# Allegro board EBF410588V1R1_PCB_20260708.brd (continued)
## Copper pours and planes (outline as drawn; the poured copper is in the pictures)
3V3_OUT on BOTTOM: 66.5,8.26 67.87,8.26 68.12,8 68.12,7.54 68.45,7.21 69.01,7.21 69.16,7.06 69.16,5.66 69.32,5.51 71.27,5.51 71.45,5.33 71.45,3.33 71.27,3.15 70.26,3.15 70.03,3.38 70.03,4.27 69.77,4.52 67.74,4.52 67.51,4.75 67.51,7.06 67.31,7.26 66.6,7.26 66.5,7.37
5V_OUT on BOTTOM: 71.17,8.26 72.54,8.26 72.69,8.1 72.69,7.8 73.3,7.19 73.74,7.19 73.86,7.06 73.86,5.79 74.17,5.49 75.11,5.49 75.29,5.31 75.29,3.43 75.03,3.17 74.12,3.17 73.86,3.43 73.86,4.45 73.48,4.83 72.31,4.83 72.21,4.93 72.21,7.14 72.01,7.34 71.32,7.34 71.17,7.49
12V on TOP: 9.53,71.93 18.69,71.93 18.97,71.65 18.97,67.54 19.13,67.39 19.74,67.39 19.74,65.58 19.53,65.38 17.5,65.38 17.5,66.09 17.07,66.52 17.07,68.96 16.87,69.16 13.61,69.16 13.41,68.96 13.41,67.54 13.59,67.36 14.25,67.36 14.25,66.4 13.97,66.12 13.97,65.56 13.79,65.38 11.91,65.38 11.91,66.4 11.48,66.83 11.48,69.8 11.2,70.08 9.53,70.08
12V on BOTTOM: 32.41,56.59 33.6,56.59 33.76,56.74 33.76,57.94 33.58,58.12 32.44,58.12 32.23,57.91 32.23,56.77
12V on BOTTOM: 88.7,8.69 90.35,8.69 90.35,7.47 90.07,7.19 86.41,7.19 86.41,8.46 88.47,8.46
12V on BOTTOM: 106.15,23.98 106.27,24.1 110.06,24.1 110.34,23.83 110.34,22.63 108.13,22.63 107.9,22.4 107.9,20.57 107.72,20.4 105.36,20.4 105.13,20.62 105.13,22.05 105.33,22.25 105.84,22.25 106.15,22.56
12V on BOTTOM: 22.48,58.78 22.17,58.78 22,58.6 22,57.45 22.38,57.07 23.67,57.07 23.67,57.89 22.81,57.89 22.66,58.04 22.66,58.6
12V on BOTTOM: 13.51,72.75 13.51,69.67 13.74,69.44 15.98,69.44 16.21,69.67 16.21,72.21 15.27,72.21 15.11,72.36 15.11,72.67 15.04,72.75
12V on ART04: 46.1,58.06 48.56,55.6 48.56,49.56 49.99,48.13 70.61,48.13 71.04,47.7 71.04,31.9 72.52,30.43 99.95,30.43 100.97,29.41 100.97,22.48 101.27,22.17 107.34,22.17 107.65,21.87 107.65,16.38 107.29,16.03 96.77,16.03 96.19,15.44 96.19,9.12 94.54,7.47 86.69,7.47 86.44,7.72 86.44,20.7 84.96,22.17 64.95,22.17 64.16,22.96 64.16,42.04 62.81,43.38 42.57,43.38 40.34,45.62 40.34,50.04 39.98,50.39 33.81,50.39 33.68,50.27 22.3,50.27 21.95,50.62 21.95,64.41 21.67,64.69 13.72,64.69 13.49,64.92 13.49,72.67 13.97,73.15 26.49,73.15 27.15,72.49 27.15,58.42 27.51,58.06
12V_OUT on BOTTOM: 76.78,7.04 76.78,5.11 76.99,4.9 77.72,4.9 78,4.62 78,3.2 78.18,3.02 79.65,3.02 79.86,3.23 79.86,6.17 80.04,6.35 82.32,6.35 82.5,6.53 82.5,8.48 78.38,8.48 78.38,7.29 78.13,7.04
GND on TOP: outline of 98 points within 1.4,49.83 94.97,83.16 ; 63 cut-outs
GND on TOP: 139.01,47.98 94.72,47.98 93.88,48.82 93.88,51.36 93.07,52.17 91.44,52.17 91.87,52.6 91.87,74.8 94.64,77.57 94.64,82.4 94.79,82.55 142.14,82.55 142.7,81.99 142.7,51.66 ; 47 cut-outs
GND on TOP: 40.67,52.17 84.86,52.17 84.94,52.1 84.94,46.79 84.56,46.41 82.35,46.41 82.09,46.15 82.09,42.75 74.8,35.46 36.42,35.46 36.32,35.36 36.32,35.13 36.2,35 36.32,35 36.32,32.28 36.53,32.08 37.57,32.08 37.62,32.03 37.62,30.78 37.8,30.78 37.8,31.85 37.81,31.84 39.54,31.84 39.55,31.85 40.92,31.85 41.4,31.37 42.57,32.54 84.86,32.54 84.94,32.46 84.94,28.47 84.73,28.27 81.79,28.27 81.64,28.12 81.64,10.92 79.76,10.92 79.76,10.79 81.64,10.79 81.64,8.59 76.76,8.59 76.33,8.15 72.92,8.15 71.55,9.53 68.66,9.53 68.22,9.09 71.73,5.59 81.64,5.59 81.64,2.44 81.18,1.98 25.93,1.98 24.71,3.2 8.86,3.2 7.44,4.62 7.44,8.43 7.04,8.84 2.01,8.84 1.3,9.55 1.3,49.94 1.52,50.16 38.66,50.16 ; 80 cut-outs
GND on TOP: 3,0.51 1.24,1.24 0.51,3 0.51,58.42 1.57,58.42 1.57,9.88 2.34,9.12 3,9.12 3.02,9.14 7.26,9.14 7.82,8.59 7.82,4.8 9.12,3.51 25.04,3.51 26.21,2.34 142.16,2.34 142.54,2.72 142.54,20.45 143.36,20.45 143.61,20.7 143.61,27.15 143.43,27.33 142.54,27.33 142.54,31.17 148.89,31.17 148.89,40.51 142.54,40.51 142.54,46.94 141.15,46.94 141,47.09 141,47.8 142.54,49.35 142.54,81.97 142.11,82.4 90.3,82.4 90.3,87.45 54.2,87.45 54.2,82.4 33.99,82.4 33.53,82.85 33.53,85.85 33.12,86.26 30.51,86.26 30.43,86.18 30.43,84.68 30.51,84.61 31.47,84.61 32.32,83.76 32.32,82.18 32.05,81.92 30.71,81.92 30.56,82.07 30.56,82.09 30.25,82.4 7.7,82.4 7.37,82.07 7.37,75.13 6.76,74.52 6.76,69.8 7.8,68.76 7.8,65.76 7.16,65.13 1.78,65.13 1.27,64.62 1.27,58.52 0.51,58.52 0.51,87 1.24,88.76 3,89.49 147,89.49 148.76,88.76 149.49,87 149.49,3 148.76,1.24 147,0.51 ; 10 cut-outs
GND on TOP: 142.7,46.18 142.7,40.64 149.02,40.64 149.02,39.65 134.9,39.65 134.9,32.03 149,32.03 149,32.66 135.53,32.66 135.53,38.96 149.07,38.96 149.07,31.01 142.67,31.01 142.67,28.3 143.48,27.48 143.48,2.74 142.88,2.13 81.69,2.13 81.28,2.54 81.28,4.98 81.66,5.36 81.66,5.38 81.69,5.41 115.04,5.41 116.81,7.19 119.43,7.19 119.63,7.39 119.63,9.6 119.56,9.68 118.14,9.68 117.5,9.04 116.2,9.04 115.37,8.2 115.24,8.33 115.24,9.27 114.58,9.93 112.55,9.93 111.48,8.86 109.27,8.86 108.56,8.15 81.28,8.15 81.28,13.34 82.04,13.34 82.04,13.36 81.28,13.36 81.28,28.14 81.48,28.35 84.73,28.35 84.58,28.5 84.58,32.41 81.1,32.41 81.08,32.44 77.8,32.44 77.7,32.54 77.7,32.77 78.13,33.2 78.16,33.2 84.58,39.62 84.58,52.02 84.84,52.27 93.6,52.27 94.03,51.84 94.03,48.95 94.69,48.29 138.35,48.29 140.49,46.15 141.2,46.15 141.22,46.18 ; 62 cut-outs
GND on BOTTOM: 51.59,83.13 51.59,76.61 53.16,75.03 53.16,58.88 72.34,58.88 72.92,58.29 83.64,58.29 84.73,57.2 84.73,50.83 85.29,50.27 98.32,50.27 98.86,50.8 98.55,51.1 98.55,58.6 97.79,59.36 95.43,59.36 95.02,59.77 95.02,60.48 96.47,61.93 106.2,61.93 108.43,59.69 108.43,51.97 145.36,51.97 146.43,53.04 146.43,80.42 143.41,83.44 51.89,83.44 ; 39 cut-outs
GND on BOTTOM: 67.84,48.77 67.84,46.05 66.98,45.19 64.57,45.19 64.57,45.54 67.79,48.77
GND on BOTTOM: 3,0.51 1.24,1.24 0.51,3 0.51,81.38 3.56,81.38 3.91,81.03 3.91,20.78 3.61,20.47 3.61,17.91 3.66,17.86 3.81,17.86 3.91,17.75 4.65,17.75 5,18.11 50.24,18.11 50.24,18.08 51.16,17.17 51.79,17.17 52.02,16.94 52.02,14.25 52.17,14.1 53.04,14.1 53.54,14.61 55.27,14.61 55.6,14.94 55.6,15.8 56.44,16.64 56.44,17.6 56.69,17.86 57.58,17.86 58.24,17.2 61.67,17.2 62.31,16.56 62.31,15.54 63.22,14.63 63.22,11.91 64.39,10.74 65.05,10.74 65.25,10.95 65.25,15.47 65.63,15.85 77.04,15.85 77.34,15.54 77.34,11.1 77.62,10.82 80.49,10.82 80.49,10.36 80.62,10.36 80.62,10.82 90.22,10.82 90.22,9.75 90.5,9.75 90.5,10.82 91.8,10.82 92.1,11.13 92.1,11.61 144.88,11.61 145.41,12.14 145.41,55.88 145.34,55.96 145.41,55.96 145.41,80.52 142.88,83.06 27.33,83.06 27.33,83.57 25.93,83.57 25.93,83.06 0.51,83.06 0.51,87 1.24,88.76 3,89.49 147,89.49 148.76,88.76 149.49,87 149.49,3 148.76,1.24 147,0.51 ; 55 cut-outs
GND on BOTTOM: 0.51,81 0.51,83.64 3.94,83.64 3.94,81
GND on BOTTOM: 3.56,55.98 3.56,82.96 3.96,83.36 51.99,83.36 52.22,83.13 52.22,82.52 52.2,82.5 52.2,75.62 53.34,74.47 53.34,54.94 52.4,54 44.42,54 40.08,58.34 37.69,58.34 34.9,55.55 3.99,55.55 ; 48 cut-outs
GND on BOTTOM: 144.32,53.14 145.85,53.14 145.85,12.19 145.08,11.43 117.78,11.43 116.23,12.98 115.27,12.98 113.72,11.43 92.28,11.43 92.1,11.61 92.1,15.7 90.4,17.4 87.22,17.4 86.69,17.93 86.69,22.96 83.79,25.86 63.2,25.86 60.1,28.96 47.62,28.96 46.33,30.25 46.33,31.7 46.69,32.05 61.34,32.05 64.21,29.18 89.31,29.18 89.69,28.8 89.69,18.47 89.84,18.31 92.74,18.31 93.12,18.69 93.12,28.73 93.47,29.08 93.55,29.08 93.95,29.49 97.64,29.49 97.87,29.72 97.87,31.6 97.89,31.6 98.07,31.78 98.81,31.78 99.01,31.57 99.01,31.06 100.33,29.74 103.84,29.74 104.44,30.35 120.83,30.35 121.44,29.74 122.1,29.74 122.1,33.68 121.64,34.14 121.64,38.91 121.56,38.99 112.95,38.99 111.43,40.51 108.74,40.51 108.56,40.69 108.56,52.15 108.74,52.32 143.51,52.32 ; 55 cut-outs
GND on BOTTOM: outline of 140 points within 3.68,17.73 122.28,59 ; 22 cut-outs
GND on GND02: 3,0.51 1.24,1.24 0.51,3 0.51,87 1.24,88.76 3,89.49 147,89.49 148.76,88.76 149.49,87 149.49,3 148.76,1.24 147,0.51 ; 1 cut-out
GND on ART03: 43.21,54.58 43.51,54.89 43.51,65.76 44.17,66.42 45.75,66.42 46.96,65.2 46.96,63.65 47.32,63.3 53.85,63.3 55.24,64.69 55.24,65.02 55.23,65.04 55.23,65.42 57.58,67.77 72.44,67.77 72.54,67.87 72.54,69.29 72.29,69.55 54.86,69.55 54.51,69.19 54.51,67.79 53.06,66.34 48.36,66.34 46.71,68 40.84,68 40.59,67.74 40.59,54.94 40.94,54.58
GND on ART03: 100.43,1.35 100.08,0.99 59.59,0.99 59.33,1.24 59.33,6.05 57.35,8.03 41.81,8.03 41.49,8.34 41.49,11.6 41.07,12.01 41.07,15.52 41.85,16.29 41.85,18.99 42.14,19.28 46.86,19.28 50.16,22.58 50.16,27.03 50.39,27.25 53.62,27.25 54.08,26.8 51.82,26.8 51.82,26.59 54.28,26.59 55.27,25.6 55.27,14.78 56.72,13.34 58.27,13.34 58.62,12.98 58.62,12.62 62.23,9.02 62.23,5.99 63.94,4.28 63.94,3.11 64.59,2.46 92.43,2.46 93.14,3.17 93.14,4.57 95.83,7.26 104.78,7.26 104.78,6.48 105.87,6.48 105.87,7.26 108.38,9.78 108.38,15.47 108.39,15.48 108.39,16.31 108.67,16.59 111.12,16.59 113.13,18.59 123.83,18.59 124.36,19.13 128.7,19.13 129.08,18.75 129.08,12.52 129.41,12.19 134.01,12.19 134.62,11.58 134.62,4.88 134.39,4.65 134.16,4.65 133.76,5.05 100.81,5.05 100.43,4.67 ; 4 cut-outs
GND on ART03: 92.28,48.49 92.28,53.67 91.52,54.43 91.52,55.85 90.97,56.4 91.67,57.1 91.67,61.14 91.26,61.54 91.21,61.54 90.63,62.13 90.63,62.51 89.64,63.5 89.64,86.44 89.85,86.65 146.57,86.65 147.45,85.78 147.45,19.23 147.27,19.05 145.8,19.05 145.29,19.56 139.17,19.56 138.63,20.09 138.63,20.14 136.6,22.17 134.72,22.17 134.21,22.68 132.11,22.68 130.81,23.98 115.87,23.98 115.85,24 99.03,24 98.25,24.79 98.25,29.59 97.51,30.33 97.51,31.55 96.75,32.31 96.75,34.25 93.79,34.25 92.38,32.84 92.38,20.04 92.02,19.68 92.02,18.06 92.13,17.96 94.26,17.96 94.49,17.73 94.49,16.81 94.72,16.59 108.69,16.59 108.71,16.56 108.71,9.47 108.05,8.81 107.42,8.81 107.05,9.18 93.33,9.18 93.04,8.89 93.04,5.79 92.66,5.41 86.84,5.41 86.59,5.66 86.59,12.52 87.07,13 88.27,13 88.29,12.98 89.15,12.98 90.3,14.12 90.3,33.73 91.06,34.49 91.06,44.02 91.05,44.03 91.05,46.49 91.03,46.51 91.03,47.24 ; 13 cut-outs
GND on ART03: 79.38,21.11 79.2,21.29 79.2,35.64 73.63,41.2 73.63,53.62 72.5,54.75 72.5,56.3 68.28,60.53 68.28,63.6 67.82,64.06 67.77,64.06 67.77,65.05 62.46,65.05 62.46,63.86 62.13,63.53 56.64,63.53 56.29,63.88 56.29,66.88 57.3,67.89 72.42,67.89 72.42,69.39 72.59,69.57 84.58,69.57 85.27,68.88 85.27,66.98 84.84,66.55 75.9,66.55 75.82,66.47 75.82,65.89 74.83,64.9 74.8,64.9 74.09,64.19 74.09,62.18 73.51,61.59 72.26,61.59 72.26,57.66 73.28,56.64 73.28,55.12 75.13,53.26 75.13,43.41 75.9,42.65 77.37,42.65 80.85,39.17 80.85,22.02 79.93,21.11 ; 1 cut-out
GND on ART03: outline of 152 points within 0.51,0.51 149.49,89.49 ; 8 cut-outs
GND on ART03: 58.34,15.42 58.34,13.21 58.37,13.21 59.18,12.4 62.61,12.4 63.88,13.67 66.07,13.67 66.07,14.88 65,15.95 58.88,15.95
GND on ART03: 68.22,45.85 67.36,44.98 66.78,44.98 66.14,44.35 66.14,42.06 65.61,41.53 65.53,41.53 65.53,35.81 67.72,33.63 67.72,25.7 68.12,25.3 68.12,20.52 72.14,16.51 72.14,11.43 72.82,10.74 72.82,9.63 74.83,7.62 76.58,7.62 77.01,7.19 79.71,7.19 82.35,9.83 82.35,12.42 83.17,13.25 83.17,13.53 86.79,17.14 88.85,17.14 90.27,18.57 90.42,18.57 90.5,18.49 90.5,14.94 89.71,14.15 84.96,14.15 84.48,13.67 84.48,12.47 83.92,11.91 83.92,11.18 84.48,10.62 84.48,6.6 84.4,6.53 76.63,6.53 76.28,6.88 72.09,6.88 71.58,7.39 71.58,11.53 70.46,12.65 70.46,16.08 66.34,20.19 66.34,30.91 64.26,32.99 64.26,41.94 63.37,42.82 63.37,47.73 62.61,47.73 62.26,48.08 62.26,49.33 62.84,49.91 63.83,49.91 64.64,50.72 65.07,50.72 65.53,50.27 67.11,50.27 68.22,49.15 ; 1 cut-out
GND on ART03: 56.11,57.84 65.66,57.84 71.4,52.1 71.4,39.37 75.39,35.38 75.39,18.08 75.67,17.81 80.87,17.81 83.59,20.52 83.59,42.75 82.7,43.64 82.7,43.79 81.36,45.14 81.36,48.77 80.82,49.3 80.82,50.22 79.48,51.56 79.48,56.41 79.81,56.74 81.28,56.74 81.76,56.26 81.76,53.26 82.4,52.63 82.4,49.81 82.17,49.58 82.17,48.84 84.05,46.96 84.96,46.96 85.14,46.79 85.14,44.65 84.72,44.23 85.01,43.94 85.01,17.17 84.48,16.64 75.01,16.64 74.35,17.3 74.35,19.48 74.33,19.49 74.33,25.51 74.07,25.78 73.49,25.78 73.29,25.98 73.29,30.37 72.03,31.62 72.03,35.64 72.01,35.64 71.7,35.94 71.7,37.26 71.15,37.82 70.1,37.82 69.77,38.15 69.77,52.2 65.41,56.57 63.88,56.57 63.5,56.95 57.94,56.95 57.73,56.74 57.73,56.44 59.79,54.38 59.79,53.54 59.54,53.29 56.06,53.29 55.55,53.8 55.55,57.28 ; 1 cut-out
GND on ART03: 76.33,44.96 80.62,44.96 80.8,45.14 80.8,48.9 79.86,49.83 76.3,49.83 76.07,49.61 76.07,45.21
GND on ART03: outline of 90 points within 1.04,30.78 90.47,86.65
GND on ART04: outline of 87 points within 0.51,0.51 149.49,89.49
GND on ART04: 146.25,20.88 146.25,23.29 149.49,23.29 149.49,20.88
GND on ART04: 76.05,39.19 76.35,39.5 106.35,39.5 106.93,40.08 106.93,56.62 107.29,56.97 113.61,56.97 114.25,56.34 114.25,31.06 114.96,30.35 122.35,30.35 122.76,29.95 122.76,25.27 122.4,24.92 111.79,24.92 111.53,25.17 111.53,25.45 111.56,25.48 111.56,26.59 111.23,26.92 107.95,26.92 107.72,27.15 107.72,30.48 107.49,30.71 76.66,30.71 76.05,31.32 ; 1 cut-out
GND on PWR05: 3,0.51 1.24,1.24 0.51,3 0.51,87 1.24,88.76 3,89.49 147,89.49 148.76,88.76 149.49,87 149.49,3 148.76,1.24 147,0.51
VBUS5V0_TYPEC on BOTTOM: 28.8,76.58 26.44,76.58 26.29,76.73 26.29,80.34 27.17,80.34 27.17,77.64 27.61,77.19 28.8,77.19
VBUS5V0_TYPEC on ART04: 26.26,87.91 42.16,87.91 42.52,87.55 42.52,80.98 41.94,80.39 26.31,80.39 25.55,81.15 25.55,87.2
VCC5V0_SYS_S5 on TOP: 53.16,17.83 53.39,17.6 53.39,15.82 53.64,15.57 53.64,11.68 52.2,11.68 52.2,15.32 51.87,15.65 51.87,16.05 51.71,16.21 50.95,16.21 50.83,16.33 50.83,17.7 50.95,17.83
VCC5V0_SYS_S5 on TOP: 10.03,58.34 10.03,56.95 10.95,56.95 11.28,56.62 11.28,52.78 11.56,52.5 13.82,52.5 13.94,52.63 13.94,53.95 13.77,54.13 13.28,54.13 13.11,54.31 13.11,58.12 12.88,58.34
VCC5V0_SYS_S5 on BOTTOM: 34.77,48.84 34.77,47.24 34.65,47.12 32.77,47.12 32.59,47.29 32.59,48.21 33.3,48.21 33.48,48.39 33.48,48.84
VCC5V0_SYS_S5 on BOTTOM: 11.38,54.79 11.38,52.6 11.53,52.45 13.77,52.45 13.94,52.63 13.94,53.87 13.74,54.08 12.5,54.08 12.32,54.25 12.32,54.66 12.19,54.79
VCC5V0_SYS_S5 on ART04: 11.66,54.56 16.36,54.56 16.59,54.33 16.59,52.55 16.94,52.2 21.29,52.2 21.67,51.82 21.67,50.11 21.92,49.86 35.1,49.86 35.89,49.07 35.89,41.22 38.66,38.46 58.22,38.46 59.46,39.7 60.15,39.7 60.33,39.52 60.33,39.14 59.49,38.3 59.49,22.07 58.85,21.44 55.32,21.44 54.84,20.95 54.84,15.57 54.03,14.76 31.06,14.76 30.53,15.29 30.53,30.4 27.91,33.02 12.29,33.02 11.81,33.5 11.81,46.91 11.35,47.37 11.35,54.25
VCC5V0_USB20_HOST on BOTTOM: 133.1,85.14 137.87,85.14 138.1,85.37 138.1,86.82 134.44,86.82 134.44,86.49 134.32,86.36 133.1,86.36
VCC5V0_USB20_HOST on ART04: 117.75,76.17 117.75,81.74 118.57,82.55 138.2,82.55 139.22,81.53 139.22,76.15 138.61,75.54 118.39,75.54
VCC5V0_USB30_HOST on BOTTOM: 116.71,86.36 117.6,86.36 118.06,86.82 119.68,86.82 119.89,86.61 119.89,85.34 119.68,85.14 116.71,85.14
VCC_1V8_S3 on TOP: 56.21,11.68 56.21,14 56.34,14.12 56.52,14.12 56.59,14.2 56.59,15.06 56.85,15.06 56.85,11.68
VCC_1V8_S3 on BOTTOM: 56.87,13.89 56.87,11.84 57.07,11.63 59.13,11.63 59.51,11.25 59.51,9.65 59.49,9.63 58.7,9.63 58.7,10.74 58.45,11 56.18,11 55.93,11.25 55.93,13.92 56.13,14.12 56.64,14.12
VCC_1V8_S3 on ART04: 57.35,16.13 57.18,15.95 55.45,15.95 55.22,15.72 55.22,12.75 55.35,12.62 56.59,12.62 56.77,12.8 56.77,13.87 57.02,14.12 62.99,14.12 63.88,15.01 63.88,41.96 62.81,43.03 42.52,43.03 40.01,45.54 40.01,48.84 39.78,49.07 38.43,49.07 38.23,48.87 38.23,45.34 42.16,41.4 61.16,41.4 62.48,40.08 62.48,19.33 61.82,18.67 57.84,18.67 57.35,18.19
VCC_3V3_S0 on TOP: 55.02,11.68 55.02,15.19 54.91,15.29 54.36,15.29 54.23,15.42 54.23,15.77 53.85,16.15 53.85,17.58 54.03,17.75 55.22,17.75 55.4,17.58 55.4,15.77 55.63,15.54 55.63,11.68
VCC_3V3_S0 on BOTTOM: 55.5,17.58 55.5,14.83 55.35,14.68 53.44,14.68 53.01,14.25 52.07,14.25 52.07,15.65 52.3,15.88 53.57,15.88 53.8,16.1 53.8,17.55 54.03,17.78 55.3,17.78
VCCA1V8_PLDO2_S0 on ART04: 55.55,16.18 56.95,16.18 57.15,16.38 57.15,18.26 57.73,18.85 61.54,18.85 62.18,19.48 62.18,39.98 60.99,41.17 42.09,41.17 37.97,45.29 37.97,49 38.25,49.28 39.75,49.28 39.9,49.43 39.9,49.99 39.75,50.14 36.45,50.14 36.17,49.86 36.17,41.45 38.94,38.68 58.06,38.68 59.33,39.95 60.3,39.95 60.6,39.65 60.6,38.94 59.69,38.02 59.69,21.82 58.98,21.11 55.65,21.11 55.27,20.73 55.27,16.46
VDD_3V3 on TOP: 114.63,43.36 117.37,43.36 117.6,43.13 117.6,42.14 117.4,41.94 114.81,41.94 114.63,42.11
VDD_3V3 on BOTTOM: 70.66,7.65 68.99,7.65 68.99,8.26 68.83,8.41 68.4,8.41 68.28,8.53 68.28,9.09 68.43,9.25 70.69,9.25 70.87,9.07 70.87,7.85
VDD_3V3 on BOTTOM: 52.07,12.95 53.21,12.95 53.34,12.83 53.34,12.5 53.52,12.32 55.12,12.32 55.24,12.19 55.24,9.14 55.02,8.92 53.77,8.92 53.59,9.09 53.59,11.05 53.11,11.53 52.22,11.53 52.07,11.68
VDD_3V3 on BOTTOM: 108.1,66.52 107.19,66.52 107.04,66.67 107.04,72.29 107.48,72.73 130.48,72.73 130.81,72.4 130.81,66.67 130.61,66.47 127.03,66.47 126.82,66.67 126.82,68.28 126.59,68.5 110.74,68.5 110.57,68.33 110.57,66.78 110.31,66.52 108.51,66.52 108.43,66.45 108.18,66.45
VDD_3V3 on BOTTOM: 35.59,67.87 36.3,67.87 36.58,68.15 36.58,68.86 36.73,69.01 39.22,69.01 39.37,68.86 39.37,67.26 38.53,67.26 38.53,68.02 38.43,68.12 37.36,68.12 37.13,67.89 37.13,67.51 36.91,67.28 35.59,67.28
VDD_3V3 on BOTTOM: 124.43,18.62 123.85,18.62 123.85,18.11 123.65,17.91 123.04,17.91 122.89,17.75 122.89,16.56 123.06,16.38 124.26,16.38 124.43,16.56
VDD_3V3 on BOTTOM: 39.55,64.85 40.34,64.85 40.46,64.97 40.46,66.01 39.85,66.01 39.85,65.53 39.75,65.43 39.55,65.43
VDD_3V3 on ART04: 76.15,70.28 76.35,70.08 76.35,67.87 76.1,67.61 75.87,67.61 75.36,67.11 75.36,57.56 75.84,57.07 82.17,57.07 82.4,56.85 82.4,53.92 82.58,53.75 88.8,53.75 89.08,54.03 89.08,61.11 88.95,61.24 88.95,61.52 89.08,61.65 89.08,68.2 91.52,70.64 91.52,73.28 91.92,73.69 108.43,73.69 108.79,73.33 108.79,66.9 108.38,66.5 95.45,66.5 95.12,66.83 94.03,66.83 93.7,66.5 93.7,46.91 93.45,46.66 78.97,46.66 78.77,46.86 78.77,53.34 78.08,54.03 71.65,54.03 71.27,54.41 71.27,67.31 70.99,67.59 58.32,67.59 57.38,66.65 57.38,59 57.99,58.39 63.58,58.39 63.83,58.65 63.83,60.58 64.1,60.85 65.91,60.85 66.13,60.63 66.14,60.63 66.14,57.28 65.19,56.32 65.19,54.27 64.8,53.87 60.58,53.87 60.3,54.15 60.3,55.58 59.97,55.91 54.94,55.91 54.66,56.18 54.66,65.53 53.67,66.52 41.55,66.52 40.97,67.11 40.97,69.47 41.78,70.28
VDD_3V3 on ART04: outline of 108 points within 11.91,1.6 145.92,68.43
VDD_5V on TOP: 10.11,32.05 10.11,29.41 11.25,29.41 11.4,29.57 11.4,30.84 11.28,30.96 10.87,30.96 10.72,31.11 10.72,32.05
VDD_5V on TOP: 48.84,54.56 48.84,56.24 49.12,56.52 50.06,56.52 50.24,56.34 50.24,54.36 50.11,54.23 49.53,54.23 49.2,54.56
VDD_5V on TOP: 10.11,14.12 11.23,14.12 11.38,13.97 11.38,12.73 11.23,12.57 10.87,12.57 10.72,12.42 10.72,11.51 10.11,11.51
VDD_5V on TOP: 15.6,58.34 15.6,56.92 16.84,56.92 16.99,56.77 16.99,52.76 17.32,52.43 19.74,52.43 19.96,52.65 19.96,53.95 19.79,54.13 19.18,54.13 18.95,54.36 18.95,58.06 18.67,58.34
VDD_5V on TOP: 10.11,50.22 10.11,47.7 9.68,47.27 9.68,46.94 9.8,46.81 10.9,46.81 11.15,47.07 11.15,49.96 10.9,50.22
VDD_5V on BOTTOM: 117.55,88.85 116.26,88.85 116.05,88.65 116.05,87 116.23,86.82 117.63,86.82 117.78,86.97 117.78,88.62
VDD_5V on BOTTOM: 133.93,88.85 132.64,88.85 132.44,88.65 132.44,87 132.61,86.82 134.01,86.82 134.16,86.97 134.16,88.62
VDD_5V on BOTTOM: 16.97,54.79 16.97,52.7 17.22,52.45 19.79,52.45 19.96,52.63 19.96,54.56 19.74,54.79
VDD_5V on BOTTOM: 26.42,59.46 26.92,59.46 27.38,59.92 29.11,59.92 29.44,59.59 29.44,58.57 29.06,58.19 26.75,58.19 26.42,58.52
VDD_5V on BOTTOM: 73.69,7.65 75.41,7.65 75.54,7.77 75.54,9.09 75.41,9.22 73.1,9.22 73,9.12 73,8.74 73.13,8.61 73.58,8.61 73.69,8.51
VDD_5V on BOTTOM: 117.83,18.62 117.25,18.62 117.25,18.06 117.09,17.91 116.43,17.91 116.26,17.73 116.26,16.51 116.38,16.38 117.68,16.38 117.83,16.54
VDD_5V on BOTTOM: 91.64,64.72 94.34,64.72 94.59,64.97 94.59,66.42 94.44,66.57 93.78,66.57 93.65,66.45 93.65,66.19 93.57,66.12 92.71,66.12 92.71,65.48 92.56,65.33 91.64,65.33
VDD_5V on BOTTOM: 10.72,42.75 10.11,42.75 10.11,45.52 9.65,45.97 9.65,47.17 9.93,47.45 10.77,47.45 11,47.22 11,46.94 10.72,46.66
VDD_5V on BOTTOM: 30.1,76.61 31.32,76.61 31.32,76.96 31.78,77.42 32.66,77.42 33.13,77.89 34.86,77.89 34.92,77.95 34.92,79.2 34.67,79.45 31.93,79.45 31.8,79.32 31.8,78.54 31.37,78.11 30.38,78.11 30.1,77.83
VDD_5V on BOTTOM: 10.11,23.44 10.11,26.09 11.23,26.09 11.38,25.93 11.38,24.69 11.23,24.54 10.85,24.54 10.69,24.38 10.69,23.44
VDD_5V on ART04: outline of 142 points within 3.76,1.57 148.72,88.54
DSI_VDD3V3 on TOP: 144.15,14.71 140.36,14.71 140.13,14.48 140.13,13.84 140.31,13.67 142.49,13.67 142.72,13.89 144.15,13.89
DSI_VDD3V3 on BOTTOM: 123.85,14.91 123.85,16.13 124.46,16.13 124.74,16.41 124.74,17.42 124.89,17.58 125.78,17.58 125.78,16.92 127.08,15.62 127.08,14.4 127.3,14.17 142.54,14.17 142.67,14.05 142.67,13.41 142.54,13.28 126.34,13.28 125.96,13.67 125.96,15.67 125.83,15.8 125.09,15.8 124.94,15.65 124.94,15.04 124.82,14.91
DSI_VDD5V on TOP: 142.85,13.69 144.15,13.69 144.15,10.9 143.94,10.69 142.32,10.69 142.09,10.92 142.09,12.04 142.27,12.22 142.7,12.22 142.85,12.37
DSI_VDD5V on BOTTOM: 117.25,14.94 117.25,16.13 117.93,16.13 118.19,16.38 118.19,17.37 118.39,17.58 119.18,17.58 119.18,16.89 119.35,16.71 120.04,16.71 120.29,16.46 120.29,13.56 120.55,13.31 122.63,13.31 123.34,12.6 143.36,12.6 143.66,12.29 143.66,10.87 143.46,10.67 142.27,10.67 142.09,10.85 142.09,11.35 141.68,11.76 122.68,11.76 122.02,12.42 119.61,12.42 119.38,12.65 119.38,15.7 119.25,15.82 118.52,15.82 118.21,15.52 118.21,15.06 118.08,14.94
HDMI_5V on BOTTOM: 99.69,65.71 99.69,66.22 99.57,66.34 96.22,66.34 96.06,66.19 96.06,64.69 97.31,64.69 97.51,64.9 97.51,65.51 97.64,65.63 99.62,65.63
MINIPCIE_3V3 on TOP: 132.11,9.17 132.11,11.91 130.68,11.91 130.68,8.41 130.89,8.2 133.73,8.2 133.91,8.38 133.91,8.89 133.76,9.04 132.23,9.04
MINIPCIE_3V3 on BOTTOM: 117.68,25.45 119.08,25.45 119.08,24.99 119.3,24.77 121.54,24.77 121.74,24.56 121.74,23.95 122.02,23.67 124.38,23.67 124.38,22.45 122.3,22.45 122.12,22.28 122.12,20.6 121.87,20.35 119.63,20.35 119.43,20.55 119.43,21.84 119.58,22 120.37,22 120.57,22.2 120.57,22.91 120.35,23.14 117.68,23.14
MINIPCIE_3V3 on ART03: 111.51,21.49 121.82,21.49 122,21.67 122,23.11 121.72,23.39 111.51,23.39 111.33,23.22 111.33,21.67
MINIPCIE_3V3 on ART03: 112.98,7.19 115.42,7.19 115.7,7.47 115.7,9.47 116.33,10.11 131.32,10.11 131.7,9.73 131.7,8.15 131.93,7.92 133.4,7.92 133.65,8.18 133.65,11.25 133.27,11.63 113.89,11.63 112.73,10.46 112.73,7.44
MINIPCIE_3V3 on ART04: 133.78,8.26 134.04,8.51 134.04,17.2 134.75,17.91 136.25,17.91 137.01,18.67 137.01,22.17 136.63,22.56 129.72,22.56 127.85,24.42 120.56,24.42 120.45,24.54 120.19,24.54 120.08,24.42 118.44,24.42 118.01,23.99 118.01,18.95 118.21,18.75 122.5,18.75 122.94,18.31 124.64,18.31 127.94,15.01 127.94,8.61 128.3,8.26
RMII0_VDD10 on TOP: 64.72,55.17 65.35,55.17 65.48,55.3 65.48,56.03 65.58,56.13 66.04,56.13 66.17,56.01 66.17,55.68 66.29,55.55 66.6,55.55 66.67,55.63 66.67,57 68.71,57 68.71,55.68 68.55,55.52 67.61,55.52 67.28,55.19 67.28,54.66 67.18,54.56 64.72,54.56
RMII0_VDD10 on ART04: 58.39,67.34 57.63,66.57 57.63,59.18 57.99,58.83 63.35,58.83 63.58,59.05 63.58,60.71 64.01,61.14 66.12,61.14 66.42,60.83 66.42,57.18 65.47,56.22 65.48,56.21 65.48,54.25 65.79,53.95 70.61,53.95 70.92,54.25 70.92,66.95 70.54,67.34
RMII1_VDD10 on TOP: 83.11,55.17 83.74,55.17 83.9,55.32 83.9,56.01 84.05,56.16 84.38,56.16 84.53,56.01 84.53,55.65 84.63,55.55 85.09,55.55 85.22,55.68 85.22,57 87.25,57 87.25,55.68 87.1,55.52 86.16,55.52 85.83,55.19 85.83,54.66 85.72,54.56 83.11,54.56
RMII1_VDD10 on ART04: 82.91,54.08 82.63,54.36 82.63,56.97 82.32,57.28 76.38,57.28 75.82,57.84 75.82,67.06 76.12,67.36 83.13,67.36 83.69,66.8 83.69,64.11 82.55,62.97 82.55,59.97 83.01,59.51 84,59.51 84.02,59.54 84.35,59.54 84.37,59.52 85.99,59.52 86.36,59.16 86.36,54.43 86,54.08
TYPEC_CC1 on BOTTOM: 37.44,66.7 38.02,66.7 38.02,67.18 38.1,67.26 38.35,67.26 38.35,67.87 37.59,67.87 37.44,67.72
TYPEC_CC2 on BOTTOM: 39.85,66.7 39.85,67.18 39.78,67.26 39.55,67.26 39.55,67.87 40.31,67.87 40.46,67.72 40.46,66.7
N16958788 on TOP: 12.85,74.68 12.85,77.01 12.45,77.42 11.89,77.42 11.58,77.72 11.58,80.85 11.2,81.23 9.07,81.23 8.69,80.85 8.69,74.98 8.99,74.68
N16959455 on TOP: 18.41,65.13 16.69,65.13 16.38,64.82 16.38,62.15 16.18,61.95 15.6,61.95 15.6,60.53 17.93,60.53 17.93,63.07 17.78,63.22 17.35,63.22 17.22,63.35 17.22,64.31 17.35,64.44 18.41,64.44
N16961177 on TOP: 12.83,65.13 11.1,65.13 10.79,64.82 10.79,62.15 10.59,61.95 10.01,61.95 10.01,60.53 12.34,60.53 12.34,63.07 12.19,63.22 11.76,63.22 11.63,63.35 11.63,64.31 11.76,64.44 12.83,64.44
N16971189 on TOP: 62.67,60.73 62.87,60.73 63.15,60.45 63.83,60.45 64.42,59.87 66.04,59.87 66.83,59.08 68.69,59.08 68.84,58.93 68.84,57.84 66.65,57.84 65.56,58.93 64.24,58.93 63.5,59.66 62.74,59.66 62.62,59.79 62.62,60.68
N16976649 on TOP: 81.08,60.73 81.28,60.73 81.56,60.45 82.25,60.45 82.83,59.87 84.45,59.87 85.24,59.08 87.1,59.08 87.25,58.93 87.25,57.84 85.06,57.84 83.97,58.93 82.65,58.93 81.92,59.66 81.15,59.66 81.03,59.79 81.03,60.68
N17018699 on TOP: 5.89,32.72 7.9,32.72 8.31,32.31 9.5,32.31 9.7,32.11 9.7,31.45 9.65,31.39 5.89,31.39
N17022868 on BOTTOM: 5.92,22.71 9.55,22.71 9.7,22.86 9.7,24.03 5.92,24.03
N17023671 on TOP: 5.92,51.54 7.39,51.54 7.52,51.41 7.52,50.8 7.67,50.65 9.55,50.65 9.7,50.5 9.7,49.61 6.12,49.61 5.92,49.81
N17024139 on BOTTOM: 5.92,41.91 8.84,41.91 9.7,42.77 9.7,43.36 6.05,43.36 5.92,43.23
N17026345 on TOP: 9.7,12.12 7.37,12.12 7.21,12.27 7.21,13.51 5.89,13.51 5.89,11.46 6.07,11.28 9.55,11.28 9.7,11.43
N17043489 on BOTTOM: 111.3,22.63 111.3,23.67 111.48,23.85 112.7,23.85 112.83,23.72 112.83,23.29 112.98,23.14 115.49,23.14 115.49,25.45 114.07,25.45 114.07,24.89 113.84,24.66 110.74,24.66 110.59,24.51 110.59,22.63
N17043505 on BOTTOM: 113.44,24.84 113.44,25.76 113.23,25.96 111.53,25.96 111.53,25.02 112.65,25.02 112.83,24.84
N17063858 on TOP: 51.64,63.17 53.26,63.17 53.26,62.26 53.37,62.15 54.28,62.15 54.28,61.54 51.64,61.54
N17241092 on BOTTOM: 82.55,9.4 84.84,9.4 84.84,10.16 84.66,10.34 82.55,10.34
N17313600 on TOP: 24.28,71.27 25.76,71.27 26.04,70.99 26.04,68.73 25.91,68.61 25.2,68.61 25.2,69.27 25.07,69.39 24.41,69.39 24.28,69.52
N17313600 on BOTTOM: 26.01,61.47 26.01,68.63 25.83,68.81 24.36,68.81 24.26,68.91 24.26,69.77 24.38,69.9 27.03,69.9 27.23,69.7 27.23,60.2 26.85,59.82 25.91,59.82 25.65,59.56 25.65,58.67 22.83,58.67 22.83,59.49 23.01,59.66 24.21,59.66
N17315365 on TOP: 30.12,71.27 31.6,71.27 31.88,70.99 31.88,68.73 31.75,68.61 31.04,68.61 31.04,69.32 30.96,69.39 30.25,69.39 30.12,69.52
N17315365 on BOTTOM: 32.23,69.93 33.07,69.09 33.07,58.7 30.23,58.7 30.23,59.66 31.6,59.66 31.85,59.92 31.85,68.58 31.62,68.81 30.33,68.81 30.12,69.01 30.12,69.8 30.25,69.93
N17617847 on TOP: 16.18,62.31 16.18,64.01 16,64.19 15.11,64.19 15.11,62.46 15.27,62.31
N17618789 on TOP: 10.59,62.31 10.59,64.01 10.41,64.19 9.53,64.19 9.53,62.46 9.68,62.31

Small or netless copper shapes (teardrops, artwork), in the pictures only: 60 on TOP, 36 on BOTTOM, 5 on GND02, 19 on ART03, 3 on ART04, 4 on PWR05

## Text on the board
Ref Des/Silkscreen Bottom: 20260708 | EBF410588V1R1 | SIM | YYWW | SD CARD | CAM4 | CAM2
User.Comments: CR_1_1
Ref Des/Silkscreen Top: 1L | 1H | 0L | 0H | A | 2A | 2B | 1A | LN | RN | 1B | LP | RP | T1OUT | GND | R1IN | T2OUT | R2IN | 3V3 | 5V | 12V | IN7 | IN6 | IN5 | IN3 | 1V8 | RX | TX | NC | U10T/R | UART10 | 232T/R | U8T/R | UART8 | SDA | SCL | CH3 | MOS | MIS | CH7 | CH6 | CLK | CSN | CAN | TYPE-C | EBF410588V1R1 | RS485 | 20260708 | RTC | MIC | RS232 | ETH0 | POWER | ETH1 | SARADC | USB3.0 | WIFI | USB2.0 HOST | IR | DC_IN | CAM3 | CAM1 | CAM0 | SPK_L | SPK_R | FAN | PHONE | MINI PCIE | PWR | SYS | GPIO | DSI | ON/OFF | MASK | REC
COMPVAL_TYPE_TOP: 2 | 80 | 79 | EBF410587V0R1 | 20250318 | MR | GND
DIMENSION: GND | RTC | RX | TX | 1 | A | 1L | 1H | CAN | 0L | 0H | 2A | 2B | RS485 | 1A | 1B | T1OUT | D | EarPhone | R1IN | RS232 | T2OUT | R2IN | ETH0 | 3V3 | POWER | OUTPUT | 5V | 12V | ETH1 | IN7 | IN6 | SARADC | IN5 | C | IN3 | 1V8 | FAN | UART10 | NC | B | UART8 | U:USB2.0 | D:USB3.0 | USB2.0 HOST | IR | E | 24 | 20240122 | EBF410529V0R1 | CAM3 | CAM1 | CAM0 | SPK_L | SPK_R | PWR | MIPI DSI | ON/OFF | MASKROM | RECOVERY | SYS | 17 | 2 | 18 | CAM4 | CAM2 | DCIN:12V
BODY_CENTER: CN1 | CN3 | CN4 | CN2 | C275 | U8 | C274 | C5 | Q1 | R99 | R7 | C86 | C114 | R23 | C83 | R8 | R98 | R58 | C17 | C18 | C68 | C39 | C119 | C271 | R24 | C84 | R56 | R57 | C259 | R112 | C263 | R105 | R95 | C21 | C126 | R94 | C261 | R89 | R90 | C265 | L13 | C127 | C107 | C262 | R107 | C256 | C56 | C22 | C104 | U7 | C99 | R20 | C57 | C58 | C32 | C105 | C63 | C65 | C62 | C97 | R54 | R52 | C198 | C247 | R104 | R103 | C225 | C226 | C242 | C237 | C207 | C221 | C220 | C222 | C206 | R55 | C205 | C223 | C236 | C224 | C134 | C117 | C109 | C108 | C111 | C233 | R92 | R64 | R93 | C230 | C232 | C96 | C91 | C92 | C93 | C238 | R62 | R63 | C243 | C240 | C215 | C188 | C187 | C186 | C200 | C120 | C141 | C140 | C210 | C189 | C216 | R27 | C116 | C106 | C138 | C100 | C180 | C179 | C178 | R85 | R84 | R83 | R29 | R30 | R41 | R28 | R45 | R47 | C152 | C153 | C195 | C171 | C158 | C191 | R33 | C157 | C155 | C182 | R44 | R43 | C166 | C197 | C151 | R46 | C143 | C147 | C190 | R34 | L16 | C273 | D3 | L15 | C7 | C268 | C9 | C74 | C82 | C44 | C48 | C10 | R6 | C73 | C183 | C177 | R4 | C135 | C184 | C176 | C11 | D1 | C16 | C136 | C80 | C45 | R5 | R26 | C89 | R25 | C90 | C113 | R15 | C267 | C47 | C40 | C15 | C66 | C69 | R14 | C38 | C87 | R19 | C46 | R21 | C13 | C77 | R16 | R106 | C270 | C258 | C257 | C76 | C28 | R11 | C255 | R22 | C239 | C260 | C125 | C14 | C78 | C23 | C67 | R13 | R10 | C27 | C231 | C79 | R12 | C30 | R97 | C55 | C35 | C31 | C266 | R17 | C264 | C60 | R111 | R18 | C61 | L14 | R96 | C115 | Y2 | C203 | C202 | R49 | C204 | C250 | C251 | R50 | C209 | R88 | C229 | C235 | C248 | C219 | C228 | C234 | C249 | R65 | C227 | C218 | C217 | C211 | C130 | C253 | R67 | C131 | C112 | C199 | C133 | R61 | C98 | C244 | C132 | C110 | C213 | C95 | C118 | C214 | C94 | C123 | C122 | C121 | C103 | C101 | C241 | C124 | C102 | R91 | Y1 | C185 | C181 | C129 | C128 | C139 | R39 | R40 | C159 | C165 | Q4 | C173 | C168 | R31 | C196 | C156 | R37 | C164 | C146 | R35 | C154 | C174 | C172 | R110 | C149 | C148 | C142 | C175 | C193 | C194 | C163 | C167 | C170 | C161 | C150 | R48 | R42 | C144 | C145 | C192 | C162 | C169 | C160 | C6 | Q3 | C208 | C254 | R51 | C212 | R32 | R36 | R38 | 2 | 80 | 79 | EBF410587V1R1 | 20260707 | YYWW
User.6: FIGURE | FINISHED_SIZE | 10.0 | 19.69 | 21.65 | 25.59 | 27.56 | 31.5 | 39.37 | 47.24 | 72.05 | 78.74 | 94.5 | 118.11 | 166.14 | 35.43 | 43.31 | 62.99 | 78.7 | 125.98 | 127.95 | 47.24x19.69 | 59.06x29.53 | 62.99x23.62 | 66.93x19.69 | 70.9x15.7 | 74.8x23.62 | 106.3x35.43 | DRILL CHART: TOP to BOTTOM | ALL UNITS ARE IN MILS | ROTATION | - | 0.000 | 90.000 | PLATED | NON-PLATED | QTY | 2256 | 2 | 19 | 18 | 26 | 9 | 53 | 8 | 22 | 4 | 1 | 3 | 7
